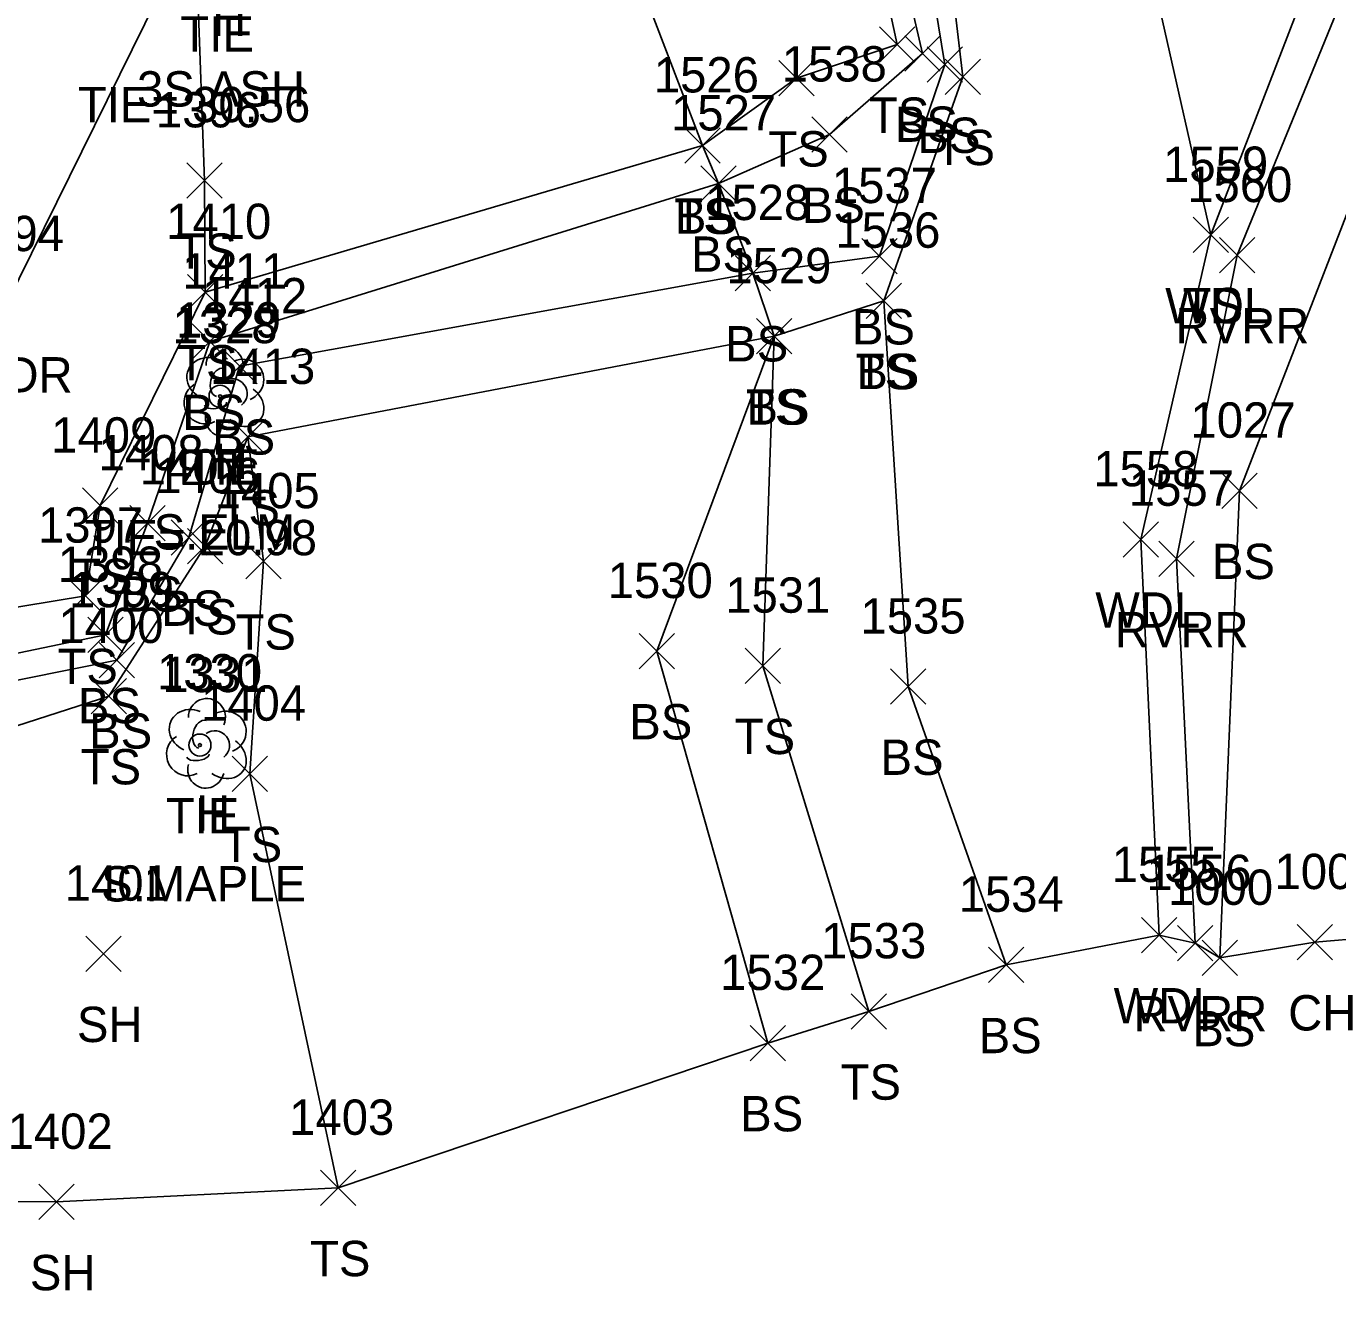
# Model space of a CAD drawing. Extents: x 1600281 to 1602254, y 862855 to 863227.
# Drawn here: x 1602032.3 to 1602106.5, y 862859.5 to 862931.1 of the extents above; entities that cross this region are included whole.
import ezdxf

# ---------------------------------------------------------------- set-up
doc = ezdxf.new("R2010")
doc.units = 0
for name, color, linetype in [('C_A', 7, 'Continuous'), ('C_C', 7, 'Continuous'), ('C_I', 7, 'Continuous'), ('CBP', 7, 'Continuous'), ('L_A', 7, 'Continuous'), ('L_C', 7, 'Continuous'), ('L_I', 7, 'Continuous'), ('L_TIC', 7, 'Continuous'), ('LAWA', 7, 'Continuous'), ('LAWE', 7, 'Continuous'), ('LELB', 7, 'Continuous'), ('LSOGP', 7, 'Continuous'), ('LTD', 7, 'Continuous')]:
    doc.layers.add(name, color=color, linetype=linetype)

msp = doc.modelspace()

# ---------------------------------------------------------------- linework, layer by layer
at = {"layer": 'CBP'}
for centre, radius in [((1602043.23, 862910.133), 0.625), ((1602043.23, 862910.133), 0.0833), ((1602042.086, 862890.387), 0.625), ((1602042.086, 862890.387), 0.0833)]:
    msp.add_circle(centre, radius, dxfattribs=at)
at = {"layer": 'L_TIC'}
for points in [[(1602080.563, 862929.038), (1602082.563, 862931.038)], [(1602082.563, 862929.038), (1602080.563, 862931.038)], [(1602081.998, 862928.527), (1602083.998, 862930.527)], [(1602083.998, 862928.527), (1602081.998, 862930.527)], [(1602083.273, 862927.901), (1602085.273, 862929.901)], [(1602085.273, 862927.901), (1602083.273, 862929.901)], [(1602074.868, 862927.131), (1602076.868, 862929.131)], [(1602076.868, 862927.131), (1602074.868, 862929.131)], [(1602084.28, 862927.211), (1602086.28, 862929.211)], [(1602086.28, 862927.211), (1602084.28, 862929.211)], [(1602076.729, 862923.942), (1602078.729, 862925.942)], [(1602078.729, 862923.942), (1602076.729, 862925.942)], [(1602069.541, 862923.323), (1602071.541, 862925.323)], [(1602071.541, 862923.323), (1602069.541, 862925.323)], [(1602069.541, 862923.323), (1602071.541, 862925.323)], [(1602071.541, 862923.323), (1602069.541, 862925.323)], [(1602041.344, 862921.347), (1602043.344, 862923.347)], [(1602043.344, 862921.347), (1602041.344, 862923.347)], [(1602070.455, 862921.172), (1602072.455, 862923.172)], [(1602072.455, 862921.172), (1602070.455, 862923.172)], [(1602070.455, 862921.172), (1602072.455, 862923.172)], [(1602072.455, 862921.172), (1602070.455, 862923.172)], [(1602098.326, 862918.262), (1602100.326, 862920.262)], [(1602100.326, 862918.262), (1602098.326, 862920.262)], [(1602098.326, 862918.262), (1602100.326, 862920.262)], [(1602100.326, 862918.262), (1602098.326, 862920.262)], [(1602079.565, 862917.061), (1602081.565, 862919.061)], [(1602081.565, 862917.061), (1602079.565, 862919.061)], [(1602099.821, 862917.119), (1602101.821, 862919.119)], [(1602101.821, 862917.119), (1602099.821, 862919.119)], [(1602072.391, 862916.1), (1602074.391, 862918.1)], [(1602074.391, 862916.1), (1602072.391, 862918.1)], [(1602072.391, 862916.1), (1602074.391, 862918.1)], [(1602074.391, 862916.1), (1602072.391, 862918.1)], [(1602041.391, 862915.03), (1602043.391, 862917.03)], [(1602043.391, 862915.03), (1602041.391, 862917.03)], [(1602041.391, 862915.03), (1602043.391, 862917.03)], [(1602043.391, 862915.03), (1602041.391, 862917.03)], [(1602079.814, 862914.532), (1602081.814, 862916.532)], [(1602081.814, 862914.532), (1602079.814, 862916.532)], [(1602079.814, 862914.532), (1602081.814, 862916.532)], [(1602081.814, 862914.532), (1602079.814, 862916.532)], [(1602041.648, 862912.223), (1602043.648, 862914.223)], [(1602043.648, 862912.223), (1602041.648, 862914.223)], [(1602073.596, 862912.524), (1602075.596, 862914.524)], [(1602075.596, 862912.524), (1602073.596, 862914.524)], [(1602073.596, 862912.524), (1602075.596, 862914.524)], [(1602075.596, 862912.524), (1602073.596, 862914.524)], [(1602073.596, 862912.524), (1602075.596, 862914.524)], [(1602075.596, 862912.524), (1602073.596, 862914.524)], [(1602043.339, 862910.825), (1602045.339, 862912.825)], [(1602045.339, 862910.825), (1602043.339, 862912.825)], [(1602043.794, 862906.826), (1602045.794, 862908.826)], [(1602045.794, 862906.826), (1602043.794, 862908.826)], [(1602043.794, 862906.826), (1602045.794, 862908.826)], [(1602045.794, 862906.826), (1602043.794, 862908.826)], [(1602099.95, 862903.784), (1602101.95, 862905.784)], [(1602101.95, 862903.784), (1602099.95, 862905.784)], [(1602035.447, 862902.94), (1602037.447, 862904.94)], [(1602037.447, 862902.94), (1602035.447, 862904.94)], [(1602038.12, 862901.94), (1602040.12, 862903.94)], [(1602040.12, 862901.94), (1602038.12, 862903.94)], [(1602040.453, 862901.138), (1602042.453, 862903.138)], [(1602042.453, 862901.138), (1602040.453, 862903.138)], [(1602094.369, 862901.033), (1602096.369, 862903.033)], [(1602096.369, 862901.033), (1602094.369, 862903.033)], [(1602041.387, 862900.65), (1602043.387, 862902.65)], [(1602043.387, 862900.65), (1602041.387, 862902.65)], [(1602044.693, 862899.793), (1602046.693, 862901.793)], [(1602046.693, 862899.793), (1602044.693, 862901.793)], [(1602096.38, 862899.93), (1602098.38, 862901.93)], [(1602098.38, 862899.93), (1602096.38, 862901.93)], [(1602034.615, 862897.845), (1602036.615, 862899.845)], [(1602036.615, 862897.845), (1602034.615, 862899.845)], [(1602035.738, 862895.625), (1602037.738, 862897.625)], [(1602037.738, 862895.625), (1602035.738, 862897.625)], [(1602036.377, 862894.193), (1602038.377, 862896.193)], [(1602038.377, 862894.193), (1602036.377, 862896.193)], [(1602066.958, 862894.711), (1602068.958, 862896.711)], [(1602068.958, 862894.711), (1602066.958, 862896.711)], [(1602072.963, 862893.88), (1602074.963, 862895.88)], [(1602074.963, 862893.88), (1602072.963, 862895.88)], [(1602081.187, 862892.704), (1602083.187, 862894.704)], [(1602083.187, 862892.704), (1602081.187, 862894.704)], [(1602035.932, 862892.166), (1602037.932, 862894.166)], [(1602037.932, 862892.166), (1602035.932, 862894.166)], [(1602043.92, 862887.769), (1602045.92, 862889.769)], [(1602045.92, 862887.769), (1602043.92, 862889.769)], [(1602095.406, 862878.641), (1602097.406, 862880.641)], [(1602097.406, 862878.641), (1602095.406, 862880.641)], [(1602097.435, 862878.183), (1602099.435, 862880.183)], [(1602099.435, 862878.183), (1602097.435, 862880.183)], [(1602104.22, 862878.239), (1602106.22, 862880.239)], [(1602106.22, 862878.239), (1602104.22, 862880.239)], [(1602035.637, 862877.584), (1602037.637, 862879.584)], [(1602037.637, 862877.584), (1602035.637, 862879.584)], [(1602098.842, 862877.347), (1602100.842, 862879.347)], [(1602100.842, 862877.347), (1602098.842, 862879.347)], [(1602086.743, 862876.954), (1602088.743, 862878.954)], [(1602088.743, 862876.954), (1602086.743, 862878.954)], [(1602078.959, 862874.321), (1602080.959, 862876.321)], [(1602080.959, 862874.321), (1602078.959, 862876.321)], [(1602073.24, 862872.53), (1602075.24, 862874.53)], [(1602075.24, 862872.53), (1602073.24, 862874.53)], [(1602048.916, 862864.333), (1602050.916, 862866.333)], [(1602050.916, 862864.333), (1602048.916, 862866.333)], [(1602032.972, 862863.538), (1602034.972, 862865.538)], [(1602034.972, 862863.538), (1602032.972, 862865.538)]]:
    msp.add_lwpolyline(points, dxfattribs=at)
at = {"layer": 'LAWA'}
for points in [[(1602013.88, 862864.604), (1602012.852, 862879.286), (1602012.389, 862885.249), (1602013.668, 862890.426), (1602013.993, 862891.89), (1602014.423, 862895.34), (1602031.133, 862915.343), (1602041.823, 862936.999), (1602041.484, 862949.365), (1602043.119, 862970.368), (1602043.104, 862998.4), (1602042.776, 863006.718), (1602043.565, 863021.702), (1602048.724, 863030.448), (1602052.915, 863023.582), (1602057.074, 863015.497), (1602062.849, 863014.974)], [(1602096.406, 862879.641), (1602095.369, 862902.033), (1602099.326, 862919.262), (1602109.634, 862945.957), (1602110.967, 862962.959), (1602110.328, 862983.187), (1602104.696, 862999.605), (1602098.833, 863009.484), (1602089.047, 863018.841), (1602087.063, 863019.481), (1602084.93, 863020.571), (1602083.846, 863020.871), (1602075.62, 863029.355), (1602062.849, 863014.974)]]:
    msp.add_lwpolyline(points, dxfattribs=at)
at = {"layer": 'LAWE'}
msp.add_lwpolyline([(1602098.435, 862879.183), (1602097.38, 862900.93), (1602100.821, 862918.119), (1602111.897, 862945.191), (1602113.655, 862964.279), (1602114.598, 862983.415), (1602109.052, 863000.365), (1602100.599, 863011.379), (1602088.422, 863022.641), (1602086.169, 863023.524), (1602076.977, 863030.193), (1602067.142, 863034.999), (1602054.868, 863040.585)], dxfattribs=at)
at = {"layer": 'LELB'}
for points in [[(1602099.842, 862878.347), (1602100.95, 862904.784), (1602110.589, 862929.642), (1602115.654, 862954.701), (1602118.276, 862973.935), (1602116.239, 862983.386), (1602108.039, 863004.489), (1602102.906, 863010.993), (1602095.897, 863019.119), (1602089.354, 863024.498), (1602085.541, 863025.448), (1602074.55, 863034.496), (1602069.632, 863039.23), (1602052.338, 863044.601)], [(1601758.874, 862935.581), (1601794.57, 862931.041), (1601823.257, 862926.647), (1601871.558, 862921.026), (1601900.015, 862918.494), (1601930.467, 862913.509), (1601956.156, 862906.35), (1601972.874, 862902.678), (1601993.622, 862897.851), (1602007.259, 862890.971), (1602013.993, 862891.89), (1602036.738, 862896.625), (1602039.12, 862902.94), (1602042.648, 862913.223), (1602071.455, 862922.172), (1602077.729, 862924.942), (1602082.998, 862929.527), (1602079.846, 862943.099), (1602074.854, 862964.036), (1602072.569, 862980.371), (1602075.414, 862992.31), (1602081.733, 863011.092), (1602084.93, 863020.571), (1602086.169, 863023.524)], [(1601758.252, 862932.382), (1601793.251, 862926.874), (1601822.781, 862921.72), (1601870.875, 862915.198), (1601899.959, 862912.838), (1601929.995, 862911.268), (1601955.114, 862904.27), (1601972.397, 862900.453), (1601993.867, 862895.104), (1602006.953, 862889.055), (1602013.668, 862890.426), (1602037.377, 862895.193), (1602041.453, 862902.138), (1602044.339, 862911.825), (1602073.391, 862917.1), (1602080.565, 862918.061), (1602084.273, 862928.901), (1602082.101, 862942.173), (1602076.793, 862963.57), (1602077.845, 862979.478), (1602084.814, 862995.174), (1602084.825, 863009.345), (1602087.063, 863019.481), (1602088.422, 863022.641)], [(1601758.889, 862937.881), (1601795.072, 862933.903), (1601823.846, 862928.868), (1601870.343, 862922.924), (1601900.351, 862921.152), (1601930.516, 862914.56), (1601956.196, 862907.256), (1601973.319, 862904.611), (1601993.849, 862899.996), (1602008.191, 862895.024), (1602014.423, 862895.34), (1602035.615, 862898.845), (1602036.447, 862903.94), (1602042.391, 862916.03), (1602070.541, 862924.323), (1602075.868, 862928.131), (1602081.563, 862930.038), (1602078.855, 862942.657), (1602073.583, 862963.521), (1602071.226, 862980.749), (1602072.263, 862993.358), (1602076.694, 863007.703), (1602078.086, 863013.394), (1602083.846, 863020.871)], [(1601994.69, 862890.807), (1602005.018, 862886.613), (1602012.389, 862885.249), (1602036.932, 862893.166), (1602042.387, 862901.65), (1602044.794, 862907.826), (1602074.596, 862913.524), (1602080.814, 862915.532), (1602085.28, 862928.211), (1602083.535, 862943.154), (1602080.901, 862962.87), (1602080.76, 862979.184), (1602088.297, 862994.751), (1602086.854, 863009.161), (1602089.047, 863018.841)], [(1602099.326, 862919.262), (1602093.331, 862945.837), (1602092.628, 862963.103), (1602092.109, 862982.585), (1602088.297, 862994.751)], [(1602061.28, 862961.826), (1602053.671, 862961.449), (1602063.628, 862942.421), (1602070.541, 862924.323), (1602071.455, 862922.172), (1602073.391, 862917.1), (1602074.596, 862913.524), (1602067.958, 862895.711), (1602074.24, 862873.53)], [(1602041.823, 862936.999), (1602042.344, 862922.347), (1602042.391, 862916.03)], [(1602087.743, 862877.954), (1602082.187, 862893.704), (1602080.814, 862915.532)], [(1602074.596, 862913.524), (1602073.963, 862894.88), (1602079.959, 862875.321)], [(1602049.916, 862865.333), (1602044.92, 862888.769), (1602045.693, 862900.793), (1602044.794, 862907.826)]]:
    msp.add_lwpolyline(points, dxfattribs=at)
at = {"layer": 'LSOGP'}
msp.add_lwpolyline([(1601903.485, 862876.386), (1601931.065, 862872.817), (1601953.144, 862869.382), (1601986.333, 862860.287), (1601993.115, 862861.834), (1602008.266, 862863.48), (1602013.88, 862864.604), (1602033.972, 862864.538), (1602049.916, 862865.333), (1602074.24, 862873.53), (1602079.959, 862875.321), (1602087.743, 862877.954), (1602096.406, 862879.641), (1602098.435, 862879.183), (1602099.842, 862878.347), (1602105.22, 862879.239), (1602114.559, 862880.024)], dxfattribs=at)
at = {"layer": 'LTD'}
for p, q in [((1602043.436, 862910.454), (1602043.436, 862910.454)), ((1602043.436, 862910.454), (1602043.436, 862910.454)), ((1602042.437, 862890.54), (1602042.437, 862890.54)), ((1602042.437, 862890.54), (1602042.437, 862890.54))]:
    msp.add_line(p, q, dxfattribs=at)
for centre in [(1602043.482, 862911.888), (1602042.484, 862891.974)]:
    msp.add_arc(centre, 1.047, 335.52715, 180.95627, dxfattribs=at)
for centre, major_axis, ratio, start_param, end_param in [((1602042.644, 862911.121), (1.21, -0.512), 0.895232, 1.570796, 4.712389), ((1602043.227, 862910.913), (-0.208, -0.792), 0.645439, 3.141593, 6.283185), ((1602044.477, 862911.038), (-1.141, -0.483), 0.949671, 1.570796, 4.712389), ((1602043.936, 862910.288), (-0.5, 0.667), 0.989748, 3.141593, 6.283185), ((1602042.352, 862909.746), (0.584, -1.042), 0.959034, 3.141593, 6.283185), ((1602044.436, 862909.621), (-1.09, 0.792), 0.841452, 1.570796, 4.712389), ((1602042.977, 862909.704), (-0.625, -0.083), 0.423636, 0, 3.141593), ((1602043.436, 862908.954), (0.265, 1.061), 0.942809, 1.570796, 4.712389), ((1602041.645, 862891.206), (1.21, -0.512), 0.895232, 1.570796, 4.712389), ((1602043.479, 862891.123), (-1.141, -0.483), 0.949671, 1.570796, 4.712389), ((1602042.229, 862890.998), (-0.208, -0.792), 0.645439, 3.141593, 6.283185), ((1602042.937, 862890.373), (-0.5, 0.667), 0.989748, 3.141593, 6.283185), ((1602041.354, 862889.831), (0.584, -1.042), 0.959034, 3.141593, 6.283185), ((1602043.437, 862889.707), (-1.09, 0.792), 0.841452, 1.570796, 4.712389), ((1602041.979, 862889.79), (-0.625, -0.083), 0.423636, 0, 3.141593), ((1602042.437, 862889.04), (0.265, 1.061), 0.942809, 1.570796, 4.712389)]:
    msp.add_ellipse(centre, major_axis=major_axis, ratio=ratio, start_param=start_param, end_param=end_param, dxfattribs=at)

# ---------------------------------------------------------------- texts
at = {"layer": 'C_A'}
for p in [(1602040.983, 862929.64), (1602041.309, 862905.133), (1602040.165, 862885.387)]:
    msp.add_text('TIE', height=2, dxfattribs=at).set_placement(p)
at = {"layer": 'C_C'}
for s, p in [('TIE= 30.56', (1602035.18, 862925.64)), ('TIE= 20.98', (1602035.561, 862901.133))]:
    msp.add_text(s, height=2, dxfattribs=at).set_placement(p)
at = {"layer": 'C_I'}
for s, p in [('1328', (1602040.538, 862913.133)), ('1331', (1602039.96, 862893.387))]:
    msp.add_text(s, height=2, dxfattribs=at).set_placement(p)
at = {"layer": 'L_A'}
for s, p in [('H', (1602042.78, 862930.524)), ('TS', (1602079.973, 862925.038)), ('BS', (1602081.439, 862924.527)), ('BS', (1602082.714, 862923.901)), ('TS', (1602074.277, 862923.131)), ('TS', (1602083.689, 862923.211)), ('BS', (1602076.17, 862919.942)), ('TS', (1602068.95, 862919.323)), ('BS', (1602068.982, 862919.323)), ('TS', (1602040.754, 862917.347)), ('BS', (1602069.896, 862917.172)), ('BS', (1602069.896, 862917.172)), ('WDL', (1602096.744, 862914.262)), ('TS', (1602097.736, 862914.262)), ('BS', (1602079.006, 862913.061)), ('RVRR', (1602097.333, 862913.119)), ('BS', (1602071.831, 862912.1)), ('BS', (1602071.831, 862912.1)), ('TS', (1602040.8, 862911.03)), ('TS', (1602040.8, 862911.03)), ('TS', (1602079.223, 862910.532)), ('BS', (1602079.255, 862910.532)), ('WDR', (1602028.496, 862910.343)), ('TS', (1602073.005, 862908.524)), ('TS', (1602073.005, 862908.524)), ('BS', (1602073.037, 862908.524)), ('BS', (1602041.089, 862908.223)), ('BS', (1602042.78, 862906.825)), ('H', (1602042.869, 862905.454)), ('TS', (1602043.203, 862902.826)), ('TS', (1602043.203, 862902.826)), ('BS', (1602099.391, 862899.784)), ('TS', (1602034.857, 862898.94)), ('BS', (1602037.561, 862897.94)), ('BS', (1602039.894, 862897.138)), ('TS', (1602040.796, 862896.65)), ('WDL', (1602092.786, 862897.033)), ('TS', (1602044.103, 862895.793)), ('RVRR', (1602093.891, 862895.93)), ('TS', (1602034.024, 862893.845)), ('BS', (1602035.179, 862891.625)), ('BS', (1602066.399, 862890.711)), ('BS', (1602035.817, 862890.193)), ('TS', (1602072.372, 862889.88)), ('BS', (1602080.627, 862888.704)), ('TS', (1602035.341, 862888.166)), ('H', (1602041.87, 862885.54)), ('TS', (1602043.33, 862883.769)), ('WDL', (1602093.823, 862874.641)), ('RVRR', (1602094.947, 862874.183)), ('CH', (1602103.708, 862874.239)), ('SH', (1602035.125, 862873.584)), ('BS', (1602086.184, 862872.954)), ('BS', (1602098.283, 862873.347)), ('TS', (1602078.368, 862870.321)), ('BS', (1602072.68, 862868.53)), ('TS', (1602048.326, 862860.333)), ('SH', (1602032.46, 862859.538))]:
    msp.add_text(s, height=2, dxfattribs=at).set_placement(p)
at = {"layer": 'L_C'}
for s, p in [('3S.ASH', (1602038.528, 862926.524)), ('S.ELM', (1602039.467, 862901.454)), ('S.MAPLE', (1602036.5, 862881.54))]:
    msp.add_text(s, height=2, dxfattribs=at).set_placement(p)
at = {"layer": 'L_I'}
for s, p in [('1538', (1602075.036, 862927.942)), ('1526', (1602067.793, 862927.323)), ('1526', (1602067.793, 862927.323)), ('1396', (1602039.596, 862925.347)), ('1527', (1602068.762, 862925.172)), ('1527', (1602068.762, 862925.172)), ('1559', (1602096.626, 862922.262)), ('1559', (1602096.626, 862922.262)), ('1537', (1602077.872, 862921.061)), ('1560', (1602097.995, 862921.119)), ('1528', (1602070.698, 862920.1)), ('1528', (1602070.698, 862920.1)), ('1410', (1602040.178, 862919.03)), ('1410', (1602040.178, 862919.03)), ('1394', (1602028.44, 862918.343)), ('1536', (1602078.066, 862918.532)), ('1536', (1602078.066, 862918.532)), ('1529', (1602071.895, 862916.524)), ('1529', (1602071.895, 862916.524)), ('1529', (1602071.895, 862916.524)), ('1411', (1602041.089, 862916.223)), ('1412', (1602042.213, 862914.825)), ('1329', (1602040.735, 862913.454)), ('1413', (1602042.668, 862910.826)), ('1413', (1602042.668, 862910.826)), ('1027', (1602098.178, 862907.784)), ('1409', (1602033.668, 862906.94)), ('1408', (1602036.349, 862905.94)), ('1407', (1602038.682, 862905.138)), ('1406', (1602039.56, 862904.65)), ('1558', (1602092.676, 862905.033)), ('1557', (1602094.687, 862903.93)), ('1405', (1602042.922, 862903.793)), ('1397', (1602032.922, 862901.845)), ('1398', (1602034.045, 862899.625)), ('1530', (1602065.179, 862898.711)), ('1399', (1602034.676, 862898.193)), ('1531', (1602071.837, 862897.88)), ('1535', (1602079.494, 862896.704)), ('1400', (1602034.074, 862896.166)), ('1330', (1602039.658, 862893.54)), ('1404', (1602042.149, 862891.769)), ('1555', (1602093.713, 862882.641)), ('1401', (1602034.432, 862881.584)), ('1556', (1602095.687, 862882.183)), ('1001', (1602102.936, 862882.239)), ('1534', (1602085.05, 862880.954)), ('1000', (1602096.905, 862881.347)), ('1533', (1602077.266, 862878.321)), ('1532', (1602071.547, 862876.53)), ('1403', (1602047.144, 862868.333)), ('1402', (1602031.201, 862867.538))]:
    msp.add_text(s, height=2, dxfattribs=at).set_placement(p)

doc.saveas('drawing.dxf')
